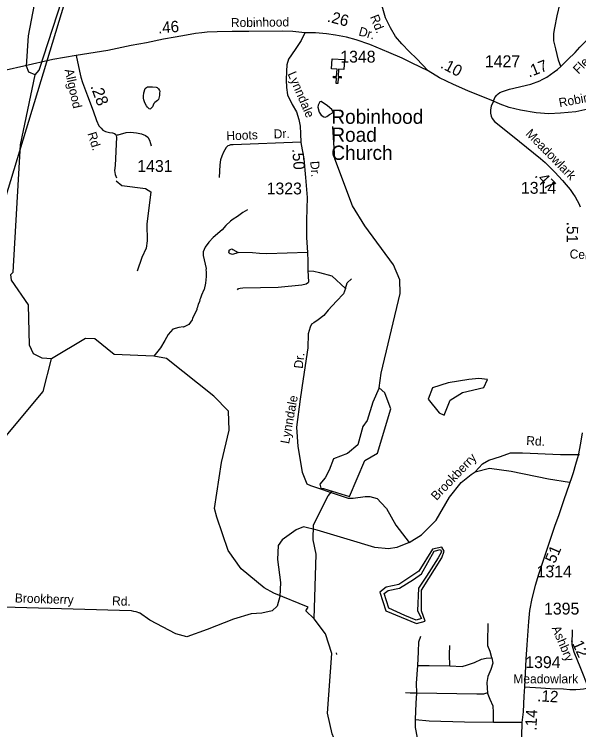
# Model space of a CAD drawing. Extents: x 1547597 to 1699558, y 810033 to 920809.
# Drawn here: x 1591150 to 1597107, y 858935 to 866479 of the extents above; entities that cross this region are included whole.
import ezdxf

# ---------------------------------------------------------------- set-up
doc = ezdxf.new("R2010")
doc.units = 0
for name, color, linetype in [('Exist Cultural Church CELL', 7, 'Continuous'), ('Exist Cultural Church Label', 7, 'Continuous'), ('Exist Hydrographic Buffer Line', 7, 'Continuous'), ('Exist Hydrographic Creek Single Shore', 7, 'Continuous'), ('Exist Hydrographic Lake Shore', 7, 'Continuous'), ('Exist Hydrographic Misc Water Feature', 7, 'Continuous'), ('Exist Road Non-System Type 51', 7, 'Continuous'), ('Exist Road Non-System Type 51 Label', 7, 'Continuous'), ('Exist Road Secondary Mileage Hundredths English Label', 7, 'Continuous'), ('Exist Road Secondary Type 41 Attributed', 7, 'Continuous'), ('Exist Road Secondary Type 51 Attributed', 7, 'Continuous'), ('Exist Road Secondary Type 51 Label', 7, 'Continuous'), ('Exist Road Secondary Type 51 Number Label', 7, 'Continuous'), ('Exist Utilities Electrical Transmission Line', 7, 'Continuous')]:
    doc.layers.add(name, color=color, linetype=linetype)

msp = doc.modelspace()

# ---------------------------------------------------------------- linework, layer by layer
at = {"layer": 'Exist Cultural Church CELL'}
msp.add_lwpolyline([(1594629.6, 865896.6), (1594572.8, 865899.8), (1594568.4, 865823.8), (1594600.3, 865821.9), (1594599.4, 865805.9), (1594567.5, 865807.8), (1594564, 865747.8), (1594548, 865748.7), (1594551.5, 865808.7), (1594519.5, 865810.6), (1594520.4, 865826.5), (1594552.4, 865824.7), (1594556.8, 865900.7), (1594499.3, 865904.1), (1594505.4, 866010.4), (1594635.8, 866002.9)], close=True, dxfattribs=at)
at = {"layer": 'Exist Hydrographic Buffer Line'}
for points in [[(1595392.6, 860090.7), (1595270.3, 860140.5), (1595102.9, 860217.5), (1595053.5, 860370.9), (1595096.2, 860401.7), (1595216.4, 860428.1), (1595361.5, 860519.9), (1595446.5, 860580), (1595581.2, 860816.4)], [(1595581.2, 860816.4), (1595647.6, 860835), (1595657.9, 860810.1), (1595622.7, 860745.9), (1595500.4, 860555.1), (1595414.7, 860427.5), (1595406.6, 860190.1), (1595448.6, 860107.3), (1595392.6, 860090.7)]]:
    msp.add_lwpolyline(points, dxfattribs=at)
at = {"layer": 'Exist Hydrographic Creek Single Shore'}
for points in [[(1591369.5, 865839.9), (1591412.6, 865888.3), (1591653.1, 866625.7), (1591582.9, 867141.5)], [(1591114.6, 863734.3), (1591139.6, 863760.1), (1591217.6, 865101.1), (1591369.5, 865839.9)], [(1595001.6, 862539.3), (1595020.6, 862696.5), (1595223.6, 863536), (1595217.7, 863677.3), (1595152.6, 863836.1), (1594849.6, 864249.3), (1594718.6, 864458.9), (1594533.6, 864955), (1594513.6, 865296.8)], [(1591543.6, 862845.7), (1591443.6, 862854.3), (1591352.6, 862898.8), (1591311.6, 862988.3), (1591301.6, 863415.4), (1591121.5, 863675.1), (1591114.6, 863734.3)], [(1593888.7, 860373.6), (1593787, 860431.8), (1593545.6, 860632), (1593406.6, 860825.2), (1593286.6, 861175.7), (1593262.6, 861268.1), (1593336.6, 861752.4), (1593416.6, 862092.2), (1593410.6, 862292.5), (1593254.6, 862453.3), (1592755.2, 862847.7), (1592624.7, 862875.5), (1592204.6, 862893.2), (1592001.1, 863056.2), (1591903, 863058.6), (1591543.6, 862845.7)], [(1587871.6, 860921), (1588739.5, 861527.1), (1589117.6, 861719.8), (1590240.5, 862113.9), (1590406.6, 862110.5), (1590514.6, 862052.5), (1590756.5, 862057.5), (1590922.5, 861995.1), (1591064.6, 862034.8), (1591454.5, 862502.9), (1591543.6, 862845.7)], [(1594504.9, 861451.6), (1594686.5, 861394.2), (1594850.6, 861774.2), (1594982.6, 861850), (1595122.7, 862318.5), (1595084.5, 862420.5), (1595059, 862487.4), (1595001.6, 862539.3)], [(1594316.4, 860103.2), (1594336.6, 860786.6), (1594305.6, 860938.3), (1594307.6, 861095.8), (1594461.6, 861401.2), (1594504.9, 861451.6)], [(1594316.4, 860103.2), (1594225.3, 860188), (1594252.9, 860226.1), (1593888.7, 860373.6)], [(1594502.6, 859738.9), (1594434.9, 859944.3), (1594316.4, 860103.2)], [(1594201.6, 856846.8), (1594679.6, 857106.3), (1594874.6, 857312.5), (1594934.6, 857429.4), (1594935.6, 857554.2), (1594697.6, 857798.6), (1594556.6, 857883.5), (1594483.6, 857983.5), (1594485.6, 858193.6), (1594597.6, 858424.4), (1594600.6, 858640.9), (1594575.6, 858667.7), (1594576.6, 858723.5), (1594503.6, 858892.4), (1594456.6, 859110), (1594502.6, 859738.9)]]:
    msp.add_lwpolyline(points, dxfattribs=at)
at = {"layer": 'Exist Hydrographic Lake Shore'}
msp.add_lwpolyline([(1595006.7, 860385.7), (1595070.6, 860187.4), (1595394.6, 860056.1), (1595486.6, 860080.5), (1595446.6, 860189.7), (1595448.6, 860406.2), (1595661.6, 860746.6), (1595687.6, 860818.3), (1595663.6, 860861.5), (1595563.6, 860837.3), (1595418.6, 860607.1), (1595207.6, 860467), (1595074.6, 860436.9), (1595006.7, 860385.7)], dxfattribs=at)
at = {"layer": 'Exist Hydrographic Misc Water Feature'}
msp.add_line((1594548.8, 859746.5), (1594550.6, 859728.4), dxfattribs=at)
for points in [[(1591369.5, 865839.9), (1591303.6, 865867.5), (1591279.6, 865933.7), (1591300.5, 866251.7), (1591445.6, 867007.1), (1591465.6, 867249.5), (1591500, 867299.9)], [(1592670.6, 865692.1), (1592681.5, 865677), (1592684.7, 865668), (1592684.3, 865647.1), (1592682.9, 865621.5), (1592676.4, 865595), (1592670.5, 865579.3), (1592663.3, 865571), (1592647.3, 865558.2), (1592634, 865547.3), (1592624.6, 865536.7), (1592616.4, 865521.9), (1592608.1, 865502.6), (1592595.7, 865487.9), (1592586.8, 865481), (1592580.2, 865480.2), (1592573.2, 865483.1), (1592555.4, 865498.9), (1592544.4, 865515.4), (1592529.6, 865545.4), (1592516.6, 865578.8), (1592514.1, 865595.1), (1592514, 865617.1), (1592518.3, 865649.2), (1592530.3, 865696), (1592535.5, 865701.1), (1592554.4, 865712.8), (1592562.4, 865714.1), (1592608, 865713.8), (1592648.1, 865711.2), (1592656.4, 865707.3), (1592670.6, 865692.1)], [(1594456.5, 865513.1), (1594388.1, 865558), (1594376.4, 865555.1), (1594355.7, 865519.8), (1594352, 865500.3), (1594368.3, 865448.3), (1594389.7, 865415.4), (1594417.1, 865397.4), (1594429.6, 865394.6), (1594450, 865401.4), (1594477.1, 865422.3), (1594515.9, 865442.2), (1594513.5, 865458.7), (1594500.7, 865476.6), (1594456.5, 865513.1)], [(1593612, 864416.3), (1593561.7, 864389), (1593507.2, 864347.6), (1593458.9, 864318.3), (1593432.7, 864298.6), (1593384.1, 864251.3), (1593345.6, 864207.8), (1593248.6, 864125.1), (1593204, 864077.6), (1593163.4, 864022.1), (1593142.8, 863974.4), (1593142.4, 863934.5), (1593174.7, 863798.1), (1593172.6, 863782.1), (1593176.4, 863766.1), (1593175.7, 863714.1), (1593169.7, 863642.9), (1593154.1, 863578.5), (1593149.4, 863573.5), (1593125.4, 863518.8), (1593117.1, 863486.9), (1593108.9, 863471), (1593104.6, 863447.2), (1593092.3, 863423.4), (1593084, 863391.5), (1593075.8, 863375.6), (1593075.7, 863367.6), (1593030.6, 863272.1), (1593026.4, 863256.3), (1592993.8, 863208.7), (1592937.5, 863181.4), (1592930.8, 863183.1), (1592885.5, 863178), (1592825.2, 863158.7), (1592772.6, 863103.5), (1592739.8, 863039.9), (1592692.9, 862960.6), (1592624.7, 862875.5)], [(1595564.2, 862540.3), (1595516.4, 862422.3), (1595634.3, 862275.7), (1595685.2, 862253.4), (1595748.9, 862409.6), (1595879.5, 862492.5), (1596105.6, 862543.5), (1596143.8, 862629.5), (1596051.4, 862639.1), (1595946.3, 862629.5), (1595729.8, 862591.3), (1595564.2, 862540.3)], [(1595001.6, 862539.3), (1594934.8, 862388.6), (1594874.3, 862194.2), (1594829.8, 862133.6), (1594775.6, 861939.2), (1594667.4, 861846.8), (1594517.7, 861792.6), (1594473.1, 861671.5), (1594431.7, 861591.8), (1594374.4, 861524.9), (1594383.9, 861483.4), (1594412.6, 861480.3), (1594504.9, 861451.6)]]:
    msp.add_lwpolyline(points, dxfattribs=at)
at = {"layer": 'Exist Road Non-System Type 51'}
msp.add_line((1596205.9, 859015.8), (1596510.6, 859013.4), dxfattribs=at)
for points in [[(1592235.1, 865207.5), (1592246.6, 865208.2), (1592330.9, 865230.9), (1592375, 865236.2), (1592440.9, 865229.3), (1592492.9, 865218.6), (1592536.6, 865199.9), (1592558.4, 865181.7), (1592577.9, 865153.2), (1592589.3, 865115.2), (1592593.1, 865093.1)], [(1594174.4, 865131.2), (1593459.5, 865102.6), (1593433.5, 865100.9), (1593417.6, 865097.2), (1593403.5, 865093.3), (1593385.1, 865073.7), (1593358.5, 865026), (1593339.9, 864984.1), (1593327.3, 864944.4), (1593320.6, 864890.5), (1593312.5, 864758.6)], [(1592225.6, 864723.9), (1592286.2, 864673.9), (1592536.2, 864643.3), (1592589.8, 864606.1), (1592548.5, 864267), (1592554.3, 864091.8), (1592543.7, 864013.5), (1592494.6, 863914.5), (1592446.9, 863770)], [(1593513.2, 863967.2), (1593489, 863957.5), (1593474.9, 863951.8), (1593463, 863947.9), (1593452.9, 863946.1), (1593441, 863948.3), (1593428.8, 863952.3), (1593419, 863960.6), (1593415.2, 863970.6), (1593417.4, 863982.6), (1593419.4, 863990.6), (1593429.6, 864000.4), (1593445.7, 864004.2), (1593457.6, 864000), (1593513.2, 863967.2)], [(1594243.5, 863967.2), (1593815.1, 863952.9), (1593739.1, 863955.9), (1593663.2, 863963), (1593513.2, 863967.2)], [(1594249.2, 863773.1), (1594310.9, 863769.7), (1594372.6, 863757.7), (1594501.1, 863721.7), (1594645.1, 863587.9)], [(1594250, 863720.6), (1594256, 863653.1)], [(1594645.1, 863587.9), (1594662.2, 863647.9), (1594710.2, 863689.1)], [(1593505.4, 863573.2), (1593513.6, 863583), (1593521.7, 863588.9), (1593533.8, 863592.8), (1593561.9, 863596.3), (1593934.1, 863600.4), (1594186.2, 863625.7), (1594230.3, 863635.9), (1594256, 863653.1)], [(1594645.1, 863587.9), (1594622.8, 863531.3), (1594549.1, 863454.1), (1594463.4, 863359.8), (1594415.4, 863301.4), (1594358.9, 863256.9), (1594312.6, 863226), (1594286.9, 863210.5), (1594271.5, 863179.7), (1594252.6, 863111.1), (1594247.5, 862963.6), (1594199.5, 862635.5), (1594168.7, 862420.1), (1594127.6, 862126.8), (1594143.1, 861921.8), (1594189.4, 861652.5), (1594239.1, 861527.3), (1594276.8, 861508.5), (1594569.8, 861412.4), (1594673.7, 861375.5), (1594726.9, 861375.5), (1594853.7, 861394.3), (1594903.4, 861392.6), (1594980.5, 861373.7), (1595021.7, 861329.2), (1595078.2, 861267.4), (1595175.9, 861090.7), (1595318, 860909.7)], [(1596014, 861654.3), (1596091.1, 861738.4), (1596158, 861776.1), (1596281.4, 861817.3), (1596387.6, 861855), (1596512.7, 861853.3), (1596913.8, 861836.1), (1597116.7, 861837.5)], [(1595318, 860909.7), (1595448.2, 860990.3), (1595600.8, 861146.4), (1595742.6, 861385.8), (1595866, 861541.8), (1595970.6, 861627.6), (1596014, 861654.3)], [(1596014, 861654.3), (1596164.8, 861693.8), (1596394.5, 861662.9), (1596788.7, 861578.8), (1597010.1, 861544.6)], [(1595318, 860909.7), (1595186.2, 860857.6), (1595098.2, 860842.9), (1594956.4, 860857.6), (1594663, 860945.7), (1594345.2, 861038.7), (1594203.4, 861072.9), (1594125.1, 861043.5), (1593978.4, 860935.9), (1593934.4, 860877.2), (1593929.5, 860730.4), (1593958.9, 860485.7), (1593954, 860338.9), (1593924.7, 860236.1), (1593870.9, 860187.2), (1593763.3, 860162.7), (1593650.8, 860157.8), (1593465, 860099.1), (1593186.3, 859991.4), (1592971.2, 859913.1), (1592853.8, 859947.4), (1592580, 860089.3)], [(1590790, 860238.9), (1592383.9, 860191.8), (1592406.7, 860183.5), (1592432.7, 860181.1), (1592472.4, 860167.6)], [(1592580, 860089.3), (1592472.4, 860167.6)], [(1596191.2, 859694.5), (1596173.6, 859759.4), (1596148.1, 859819), (1596146, 859859.4), (1596152.3, 860055)], [(1595409.9, 859613.4), (1595417.3, 859756), (1595419.7, 859861.7), (1595441.8, 859923.2)], [(1595746.5, 859608.4), (1595744, 859728.9), (1595746.5, 859822.4)], [(1595746.5, 859608.4), (1595876.7, 859601.1), (1595933.2, 859618.3), (1596006.9, 859645.3), (1596080.6, 859677.3), (1596129.8, 859689.6), (1596191.2, 859694.5)], [(1596191.2, 859694.5), (1596201, 859635.5), (1596178.9, 859569.1), (1596147, 859497.8), (1596137.1, 859431.4), (1596139.6, 859372.4), (1596144.5, 859323.2)], [(1595400.1, 859320.7), (1595395.1, 859426.5), (1595409.9, 859613.4)], [(1595409.9, 859613.4), (1595527.8, 859613.4), (1595746.5, 859608.4)], [(1595400.1, 859320.7), (1595328.8, 859320.7), (1595279.7, 859325.6)], [(1595384.8, 859043.1), (1595390.2, 859215), (1595400.1, 859320.7)], [(1596144.5, 859323.2), (1596100.3, 859310.9), (1596031.5, 859310.9), (1595400.1, 859320.7)], [(1596205.9, 859015.8), (1596205.9, 859119.1), (1596203.5, 859183), (1596174, 859251.9), (1596144.5, 859323.2)], [(1595410.4, 858734.5), (1595405.2, 858849), (1595382.9, 858959.3), (1595384.8, 859043.1)], [(1595384.8, 859043.1), (1595527.7, 859027.7), (1595900.2, 859017.5), (1596205.9, 859015.8)]]:
    msp.add_lwpolyline(points, dxfattribs=at)
at = {"layer": 'Exist Road Secondary Type 41 Attributed'}
msp.add_lwpolyline([(1591804.2, 866045.7), (1591838.7, 865878.2), (1591851.2, 865817.1), (1591869, 865759.9), (1591923.4, 865618.4), (1591981.4, 865461.7), (1592017.6, 865357.6), (1592043.6, 865302.7), (1592066.5, 865277.7), (1592086, 865255.5), (1592113.8, 865243.8), (1592154.5, 865233), (1592187.4, 865228), (1592209.4, 865220.6), (1592221.3, 865209.8), (1592230.4, 865184.9), (1592215.1, 864883.3), (1592208.9, 864833.5), (1592215.1, 864788.2), (1592228.7, 864753.7)], dxfattribs=at)
at = {"layer": 'Exist Road Secondary Type 51 Attributed'}
for points in [[(1595518.5, 865883.2), (1595394.3, 866013.8), (1595321.1, 866084), (1595241.4, 866166.8), (1595174.6, 866246.5), (1595120.4, 866335.7), (1595069.5, 866440.9), (1595040.8, 866539.7), (1594986.7, 866734.1), (1594942.1, 866899.8), (1594901.2, 867067.6)], [(1596916.7, 865930.2), (1596893.4, 865993.9), (1596863.9, 866115.2), (1596845.8, 866198.5), (1596844.1, 866239.7), (1596844.1, 866278), (1596853.8, 866335.2), (1596878.9, 866463.6), (1596909.3, 866598)], [(1596916.7, 865930.2), (1596990.7, 866002.7), (1597068.9, 866076.3), (1597119.8, 866133.3), (1597185.9, 866198.9), (1597305.7, 866313.9), (1597329, 866335.5), (1597422, 866409.5), (1597456.8, 866434.1), (1597509.2, 866464.1), (1597553.2, 866485.4), (1597646.6, 866517.5), (1597706.1, 866532.8), (1597761.6, 866541.2), (1597794.2, 866544.2), (1597831.6, 866545.6), (1597885.4, 866543.6), (1597995.5, 866533.5), (1598178.7, 866508.3), (1598275.2, 866493.1), (1598410.4, 866470.9)], [(1594217.6, 866284.5), (1594090, 866296.9), (1593981.5, 866301.1), (1593625, 866296.7), (1593450.9, 866297.2), (1593290.8, 866295.5), (1593186.6, 866289), (1593128.4, 866281.9), (1593062.5, 866276.9), (1592968.1, 866260.2), (1592847.8, 866237.8), (1592725.5, 866215.7), (1592546.8, 866178.3), (1592384.3, 866150.5), (1592137.3, 866098.1), (1591804.2, 866045.7)], [(1594217.6, 866284.5), (1594176.2, 866203.3), (1594114.4, 866108.5), (1594045.8, 866007.6), (1594028.1, 865946.9), (1594023, 865878.7), (1594020.5, 865787.8), (1594023, 865706.9), (1594033.1, 865631.1), (1594083.6, 865527.5), (1594129.1, 865449.2), (1594154.3, 865370.9), (1594167, 865300.1), (1594169.5, 865221.8), (1594174.5, 865128.3), (1594204.8, 864953.5), (1594225, 864759), (1594241.2, 864548.8), (1594233.6, 864309), (1594233.6, 864124.9), (1594243.5, 863967.2), (1594246.7, 863875.1), (1594249.2, 863773.1), (1594250, 863720.6)], [(1595518.5, 865883.2), (1595349.7, 865962.9), (1595244.6, 866017), (1595104.5, 866077.6), (1594900.7, 866160.4), (1594757.3, 866211.4), (1594656.3, 866238.5), (1594538.9, 866258.5), (1594445.1, 866274.4), (1594327.4, 866282.4), (1594217.6, 866284.5)], [(1591804.2, 866045.7), (1591558.6, 866002.1), (1591252.7, 865930.9), (1591063.9, 865889.5), (1590991.5, 865872.6), (1590806.9, 865839.3), (1590486, 865780), (1590344.2, 865770.1)], [(1596206.7, 865562.5), (1595935.8, 865672.9), (1595786.1, 865739.8), (1595636.4, 865809.9), (1595518.5, 865883.2)], [(1596206.7, 865562.5), (1596222.6, 865600.1), (1596241.1, 865625.2), (1596256.5, 865639.7), (1596274.5, 865654.3), (1596302.3, 865666.2), (1596376.7, 865689.5), (1596600.9, 865742.7), (1596695.2, 865779.1), (1596720.5, 865792.3), (1596768.7, 865816.6), (1596810.2, 865844.3), (1596846.7, 865870.8), (1596881.5, 865897.6), (1596916.7, 865930.2)], [(1596206.7, 865562.5), (1596184.2, 865512), (1596176.3, 865471.5), (1596174.5, 865435.3), (1596184.2, 865403.6), (1596193.9, 865379.8), (1596217.7, 865348.1), (1596407.1, 865198.4), (1596631.3, 865018), (1596704, 864958.5), (1596751.1, 864916.2), (1596801.8, 864868), (1596853.3, 864814.5), (1596935.2, 864726.2), (1596973.1, 864681.2), (1597015.9, 864632.1), (1597046.2, 864589), (1597070, 864555.9), (1597090.3, 864516.9), (1597106.6, 864484.3), (1597120.7, 864448.2)], [(1597298.1, 865498.8), (1597074.7, 865451.4), (1596914.5, 865435.6), (1596792.7, 865428.8), (1596657.7, 865439.5), (1596493, 865466.8), (1596371.4, 865497.7), (1596277.2, 865531.1), (1596206.7, 865562.5)], [(1597141.8, 862065.7), (1597126.5, 861958), (1597100.4, 861827.8), (1597074.4, 861730.9), (1597047.1, 861645), (1597033.7, 861601.5), (1596948.5, 861358.3), (1596897.8, 861202.3), (1596852.9, 861076.4), (1596795.6, 860909.4), (1596752, 860782.1), (1596682.4, 860571.8), (1596645.5, 860454.1), (1596613.3, 860319.4), (1596589, 860192.6), (1596576.7, 860075.8), (1596558.6, 859830.5), (1596550.3, 859679.4), (1596536.4, 859388.5)], [(1597209, 859378.3), (1597128.1, 859579.4), (1597058.1, 859752.4), (1597038.4, 859831.3), (1597040.6, 859989)], [(1596536.4, 859388.5), (1596528.7, 859288.8), (1596521, 859123), (1596507.5, 859012.5), (1596498.8, 858721.9)], [(1596536.4, 859388.5), (1596705.7, 859375.6), (1596804.3, 859370.1), (1596947.6, 859364.7), (1597011.9, 859359.8), (1597078, 859360.3), (1597121.6, 859361.2), (1597158.1, 859365.8), (1597209, 859378.3)]]:
    msp.add_lwpolyline(points, dxfattribs=at)
at = {"layer": 'Exist Utilities Electrical Transmission Line'}
msp.add_lwpolyline([(1595074.8, 882528.9), (1594795.4, 882224.2), (1594492.3, 881911.7), (1594314.2, 881725.8), (1594181.7, 881585.2), (1591756.7, 879036.3), (1591646.3, 875142), (1590597.3, 874408.7), (1590660.9, 873411.3), (1590633.8, 873059.7), (1590510, 871286.5), (1590671.8, 869193.1), (1591400.6, 867299.4), (1591680.4, 866599), (1590226.6, 861827.8), (1590099.7, 859136.4), (1590298, 857488.7)], dxfattribs=at)

# ---------------------------------------------------------------- texts
at = {"layer": 'Exist Cultural Church Label'}
for s, p in [('Robinhood ', (1594496.3, 865324.2)), ('Road ', (1594496.3, 865134.2)), ('Church', (1594496.3, 864944.2))]:
    msp.add_text(s, height=150, dxfattribs=at).set_placement(p)
at = {"layer": 'Exist Road Non-System Type 51 Label'}
for s, rotation, p in [('Dr.', 2.29681, (1593889.6, 865169.1)), ('Hoots', 2.29681, (1593390.2, 865149)), ('Dr.', 83.48356, (1594193.9, 862738.6)), ('Lynndale', 79.46852, (1594049.7, 861944.2)), ('Rd.', 357.14561, (1596551.3, 861937.3)), ('Brookberry', 46.23609, (1595605.8, 861346.2)), ('Brookberry', 358.3074, (1591154.9, 860277.3)), ('Rd.', 358.3074, (1592181, 860247))]:
    msp.add_text(s, height=95, rotation=rotation, dxfattribs=at).set_placement(p)
at = {"layer": 'Exist Road Secondary Mileage Hundredths English Label'}
for s, height, rotation, p in [('.26', 120, 345.61422, (1594446, 866403.4)), ('.46', 120, 4.33872, (1592670.7, 866276.3)), ('.10', 120, 332.35411, (1595639.1, 865919.5)), ('.17', 120, 21.35461, (1596582.8, 865811.4)), ('.28', 125, 290.30629, (1591952.4, 865720)), ('.50', 120, 273.80261, (1594083.9, 865058.8)), ('.47', 120, 312.73047, (1596636.4, 864772.6)), ('.51', 120, 269.5939, (1596981.5, 864291.7)), ('.51', 120, 66.90394, (1596838.5, 860640.2)), ('.12', 120, 294.27936, (1597017.4, 859886.5)), ('.12', 120, 356.33289, (1596666.7, 859235.8)), ('.14', 120, 87.63732, (1596660.8, 858924.1))]:
    msp.add_text(s, height=height, rotation=rotation, dxfattribs=at).set_placement(p)
at = {"layer": 'Exist Road Secondary Type 51 Label'}
for s, rotation, p in [('Rd.', 291.92865, (1594902.7, 866452.7)), ('Robinhood', 0.71526, (1593436.8, 866343.5)), ('Dr.', 344.399, (1594777.9, 866258.2)), ('Fleetwood', 46.05194, (1597104.4, 865843.1)), ('Allgood', 282.4833, (1591681.1, 865893.2)), ('Lynndale', 293.17753, (1594032.8, 865851.7)), ('Robinhood', 10.98407, (1596906.2, 865497.7)), ('Meadowlark', 314.38591, (1596539.8, 865213.4)), ('Rd.', 287.2032, (1591921.5, 865222.1)), ('Dr.', 273.80261, (1594273.7, 864928.9)), ('Century Oaks Ct.', 356.8925, (1597008.8, 863906.1)), ('Ashbry', 293.18169, (1596819.8, 860007.2))]:
    msp.add_text(s, height=95, rotation=rotation, dxfattribs=at).set_placement(p)
msp.add_text('Meadowlark ', height=95, dxfattribs=at).set_placement((1596416.1, 859424.1))
at = {"layer": 'Exist Road Secondary Type 51 Number Label'}
for s, p in [('1348', (1594590.8, 865969.7)), ('1427', (1596117, 865921.2)), ('1431', (1592448.6, 864816.9)), ('1323', (1593813.5, 864579.6)), ('1314', (1596497.1, 864586.5)), ('1314', (1596662.3, 860541.1)), ('1395', (1596741.2, 860149.4)), ('1394', (1596543.1, 859584.7))]:
    msp.add_text(s, height=125, dxfattribs=at).set_placement(p)

doc.saveas('drawing.dxf')
